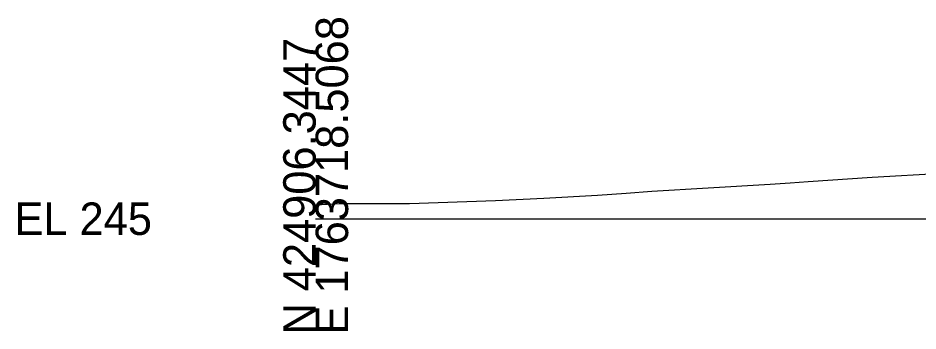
# Model space of a CAD drawing. Extents: x -26 to 3203, y -11010 to 4024.
# Drawn here: x 1974.3 to 2052, y 3992.9 to 4019.9 of the extents above; entities that cross this region are included whole.
import ezdxf

# ---------------------------------------------------------------- set-up
doc = ezdxf.new("R2010")
doc.units = 0
for name, color, linetype in [('Default', 7, 'Continuous'), ('Exist Cross Section Cell', 7, 'Continuous'), ('Exist XS Ground Line', 7, 'Continuous')]:
    doc.layers.add(name, color=color, linetype=linetype)

msp = doc.modelspace()

# ---------------------------------------------------------------- linework, layer by layer
at = {"layer": 'Exist Cross Section Cell'}
msp.add_line((2000, 4002.617), (2100, 4002.617), dxfattribs=at)
at = {"layer": 'Exist XS Ground Line'}
msp.add_lwpolyline([(2000, 4003.818), (2002.015, 4003.922), (2007.158, 4003.916), (2007.429, 4003.916), (2007.75, 4003.935), (2007.773, 4003.933), (2008.085, 4003.941), (2015.512, 4004.193), (2019.708, 4004.383), (2024.338, 4004.661), (2026.788, 4004.809), (2029.008, 4004.98), (2033.867, 4005.283), (2039.228, 4005.608), (2040.947, 4005.706), (2042.504, 4005.828), (2048.026, 4006.207), (2054.119, 4006.551)], dxfattribs=at)
msp.add_lwpolyline([(2000, 4003.818), (2002.015, 4003.922), (2007.158, 4003.916), (2007.429, 4003.916), (2007.75, 4003.935), (2007.773, 4003.933), (2008.085, 4003.941), (2015.512, 4004.193), (2019.708, 4004.383), (2024.338, 4004.661), (2026.788, 4004.809), (2029.008, 4004.98), (2033.867, 4005.283), (2039.228, 4005.608), (2040.947, 4005.706), (2042.504, 4005.828), (2048.026, 4006.207), (2054.119, 4006.551)], dxfattribs=at)
msp.add_lwpolyline([(2000, 4003.818), (2002.015, 4003.922), (2007.158, 4003.916), (2007.429, 4003.916), (2007.75, 4003.935), (2007.773, 4003.933), (2008.085, 4003.941), (2015.512, 4004.193), (2019.708, 4004.383), (2024.338, 4004.661), (2026.788, 4004.809), (2029.008, 4004.98), (2033.867, 4005.283), (2039.228, 4005.608), (2040.947, 4005.706), (2042.504, 4005.828), (2048.026, 4006.207), (2054.119, 4006.551)], dxfattribs=at)
msp.add_lwpolyline([(2000, 4003.818), (2002.015, 4003.922), (2007.158, 4003.916), (2007.429, 4003.916), (2007.75, 4003.935), (2007.773, 4003.933), (2008.085, 4003.941), (2015.512, 4004.193), (2019.708, 4004.383), (2024.338, 4004.661), (2026.788, 4004.809), (2029.008, 4004.98), (2033.867, 4005.283), (2039.228, 4005.608), (2040.947, 4005.706), (2042.504, 4005.828), (2048.026, 4006.207), (2054.119, 4006.551)], dxfattribs=at)
msp.add_lwpolyline([(2000, 4003.818), (2002.015, 4003.922), (2007.158, 4003.916), (2007.429, 4003.916), (2007.75, 4003.935), (2007.773, 4003.933), (2008.085, 4003.941), (2015.512, 4004.193), (2019.708, 4004.383), (2024.338, 4004.661), (2026.788, 4004.809), (2029.008, 4004.98), (2033.867, 4005.283), (2039.228, 4005.608), (2040.947, 4005.706), (2042.504, 4005.828), (2048.026, 4006.207), (2054.119, 4006.551)], dxfattribs=at)

# ---------------------------------------------------------------- texts
at = {"layer": 'Default'}
msp.add_text('-', height=0.0001, dxfattribs=at).set_placement((2000, 4002.617))
at = {"layer": 'Exist Cross Section Cell'}
for s, p in [('E 1763718.5068', (2002.8, 3992.617)), ('N 424906.3447', (2000, 3992.617))]:
    msp.add_text(s, height=2.8, rotation=90, dxfattribs=at).set_placement(p)
msp.add_text('EL 245', height=2.8, dxfattribs=at).set_placement((1974, 4001.217))

doc.saveas('drawing.dxf')
